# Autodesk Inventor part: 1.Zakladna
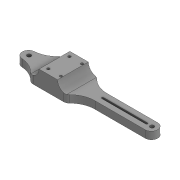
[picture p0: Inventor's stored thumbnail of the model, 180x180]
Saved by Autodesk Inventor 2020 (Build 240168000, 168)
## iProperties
Created: 2022-04
Part Number: 1.Zakladna
Material: Generic
Document SubType Name: Modeling
Designer: marti
Density: 1 g/cm^3
Appearance: Default(2)
Author: marti
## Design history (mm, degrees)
sketch "Sketch1"
  geometry: L1 (65, -25)-(-65, -25); L2 (-65, -25)-(-65, 25); L3 (-65, 25)-(65, 25); L4 (65, 25)-(65, -25); L5 (65, -25)-(-65, 25); L6 (-65, -25)-(65, 25); 1 further point
  constraints: 12 end point, 2 midpoint, 2 parallel, 1 horizontal, 1 perpendicular
  dimensions: "d0" = 130 distance of L2.end L3.end; "d1" = 50 distance of L1.end L2.end
extrude "Extrusion1" new body sketch "Sketch1" distance "d2" = 12; taper "d3" = 0 deg
sketch "Sketch2"
  geometry: L1 (-65, 25)-(-65, -25) reference; L2 (-65, -25)-(65, -25) reference; L3 (-65, 25)-(-35, 25); L4 (-35, 25)-(-35, -25); L5 (-35, -25)-(-65, -25); L6 (-65, -25)-(-65, 25); 1 further point
  constraints: 8 end point, 2 parallel, 1 horizontal, 1 perpendicular, 1 point on line
  dimensions: "d4" = 30 distance of L4.end L5.end
extrude "Extrusion2" join sketch "Sketch2" distance "d5" = 14.1; taper "d6" = 0 deg
fillet "Fillet2" dims "d32" = 14.2
sketch "Sketch4"
  geometry: L1 (-35, -25)-(-35, 25) reference; L2 (-35, 0)-(-50, 0); L3 (-65, 15)-(-35, 15); L4 (-35, 15)-(-35, -15); L5 (-35, -15)-(-65, -15); L6 (-65, -15)-(-65, 15); L7 (-65, 15)-(-35, -15); L8 (-35, 15)-(-65, -15); L9 (-35, 25)-(-20.8, 25) reference; L10 (-65, 25)-(-65, -25) reference; L11 (65, 25)-(-65, 25) reference; C1 r 2.1 at (-37.5, 17.2); C2 r 2.1 at (-37.5, -17.2); 5 further points
  constraints: 14 end point, 3 midpoint, 2 centre point, 2 horizontal, 2 parallel, 1 perpendicular
  dimensions: "d34" = 15 distance of L2.start L2.end; "d35" = 30 distance of L4.end L5.end; "d36" = 30 distance of L3.end L4.end; "d37" = 4.2 diameter of C1; "d38" = 2.5 distance from line of L1 C1.centre; "d39" = 2.2 distance from line of L3 C1.centre; "d40" = 4.2 diameter of C2 (= d37); "d41" = 2.2 distance from line of L5 C2.centre (= d39); "d42" = 2.5 distance from line of L1 C2.centre (= d38)
extrude "Extrusion4" cut sketch "Sketch4" distance "d43" = 10; taper "d44" = 0 deg
sketch "Sketch8"
  geometry: L1 (-65, -25)-(-65, 25) reference; L2 (-65, 25)-(65, 25) reference; L3 (-41.3, 21)-(-33.7, 21); L4 (-33.7, 21)-(-33.7, 13.4); L5 (-33.7, 13.4)-(-41.3, 13.4); L6 (-41.3, 13.4)-(-41.3, 21); L7 (-41.3, 21)-(-33.7, 13.4); L8 (-33.7, 21)-(-41.3, 13.4); L9 (-33.7, 15.006)-(-37.5, 12.812); L10 (-37.5, 12.812)-(-41.3, 15.006); L11 (-41.3, 15.006)-(-41.3, 19.394); L12 (-41.3, 19.394)-(-37.5, 21.588); L13 (-37.5, 21.588)-(-33.7, 19.394); L14 (-33.7, 19.394)-(-33.7, 15.006); L15 (-41.3, -13.4)-(-33.7, -13.4); L16 (-33.7, -13.4)-(-33.7, -21); L17 (-33.7, -21)-(-41.3, -21); L18 (-41.3, -21)-(-41.3, -13.4); L19 (-41.3, -13.4)-(-33.7, -21); L20 (-33.7, -13.4)-(-41.3, -21); L21 (-33.7, -19.394)-(-37.5, -21.588); L22 (-37.5, -21.588)-(-41.3, -19.394); L23 (-41.3, -19.394)-(-41.3, -15.006); L24 (-41.3, -15.006)-(-37.5, -12.812); L25 (-37.5, -12.812)-(-33.7, -15.006); L26 (-33.7, -15.006)-(-33.7, -19.394); L27 (-37.5, 17.2)-(-57.8, 17.2); L28 (-61.6, 21)-(-54, 21); L29 (-54, 21)-(-54, 13.4); L30 (-54, 13.4)-(-61.6, 13.4); L31 (-61.6, 13.4)-(-61.6, 21); L32 (-61.6, 21)-(-54, 13.4); L33 (-54, 21)-(-61.6, 13.4); L34 (-54, 15.006)-(-57.8, 12.812); L35 (-57.8, 12.812)-(-61.6, 15.006); L36 (-61.6, 15.006)-(-61.6, 19.394); L37 (-61.6, 19.394)-(-57.8, 21.588); L38 (-57.8, 21.588)-(-54, 19.394); L39 (-54, 19.394)-(-54, 15.006); L40 (-37.5, -17.2)-(-57.8, -17.2); L41 (-61.6, -13.4)-(-54, -13.4); L42 (-54, -13.4)-(-54, -21); L43 (-54, -21)-(-61.6, -21); L44 (-61.6, -21)-(-61.6, -13.4); L45 (-61.6, -13.4)-(-54, -21); L46 (-54, -13.4)-(-61.6, -21); L47 (-54, -19.394)-(-57.8, -21.588); L48 (-57.8, -21.588)-(-61.6, -19.394); L49 (-61.6, -19.394)-(-61.6, -15.006); L50 (-61.6, -15.006)-(-57.8, -12.812); L51 (-57.8, -12.812)-(-54, -15.006); L52 (-54, -15.006)-(-54, -19.394); C1 r 2.1 at (-37.5, -17.2) reference; C2 r 2 at (-37.5, -17.2); C3 r 2.1 at (-37.5, 17.2) reference; C4 r 2 at (-37.5, 17.2); 23 further points
  constraints: 100 end point, 16 midpoint, 8 parallel, 6 coincident, 5 horizontal, 5 perpendicular, 2 centre point, 52 other
  dimensions: "d58" = 7.6 distance of L4.end L5.end; "d59" = 7.6 distance of L3.end L4.end (= d58); "d60" = 7.6 distance of L16.end L17.end (= d58); "d61" = 7.6 distance of L15.end L16.end (= d58); "d62" = 20.3 distance of L27.start L27.end; "d63" = 7.6 distance of L29.end L30.end (= d58); "d64" = 7.6 distance of L28.end L29.end (= d58); "d65" = 20.3 distance of L40.start L40.end; "d66" = 7.6 distance of L42.end L43.end (= d58); "d67" = 7.6 distance of L41.end L42.end (= d58)
extrude "Extrusion6" cut sketch "Sketch8" distance "d68" = 17; taper "d69" = 0 deg
pattern_linear "Rectangular Pattern1" dims "d72" = 20.3
sketch "Sketch11"
  geometry: L1 (-65, -25)-(-65, 25) reference; L2 (-65, 25)-(-105, 25); L3 (-105, 25)-(-105, -25); L4 (-105, -25)-(-65, -25); L5 (-65, -25)-(-65, 25); L6 (65, 25)-(95, 25); L7 (95, 25)-(95, -25); L8 (95, -25)-(65, -25); L9 (65, -25)-(65, 25); 2 further points
  constraints: 16 end point, 4 parallel, 2 horizontal, 2 perpendicular
  dimensions: "d80" = 40 distance of L4.end L3.end; "d81" = 30 distance of L7.end L8.end
extrude "Extrusion8" join sketch "Sketch11" distance "d82" = 12; taper "d83" = 0 deg
sketch "Sketch12"
  geometry: L1 (95, -25)-(95, 25) reference; L2 (13.039, 1.5)-(85.139, 1.5); L3 (13.039, -1.5)-(85.139, -1.5); L4 (-20.8, -25)-(95, -25) reference; L5 (95, 25)-(-20.8, 25) reference; A1 r 1.5 centre (13.039, 0) between (13.039, 1.5) and (13.039, -1.5); A2 r 1.5 centre (85.139, 0) between (85.139, 1.5) and (85.139, -1.5); 3 further points
  constraints: 4 end point, 4 point on circle, 2 centre point, 2 tangent, 1 horizontal
  dimensions: "d87" = 3 diameter of A1; "d89" = 3 diameter of A2 (= d87); "d173" = 23.5 distance between parallel lines of L4 L3; "d174" = 72.1 distance of L2.start L2.end; "d175" = 23.5 distance between parallel lines of L2 L5
extrude "Extrusion9" cut sketch "Sketch12" distance "d90" = 12; taper "d91" = 0 deg
sketch "Sketch13"
  geometry: L1 (12.573, 2.25)-(85.139, 2.25); L2 (12.573, -2.25)-(85.139, -2.25); A1 r 2.25 centre (12.573, 0) between (12.573, 2.25) and (12.573, -2.25); A2 r 1.5 centre (85.139, 0) between (85.139, -1.5) and (85.139, 1.5) reference; A3 r 2.25 centre (85.139, 0) between (85.139, 2.25) and (85.139, -2.25); 1 further point
  constraints: 4 end point, 4 point on circle, 2 centre point, 2 tangent, 1 coincident
  dimensions: "d92" = 4.5 diameter of A1; "d93" = 4.5 diameter of A3 (= d92)
extrude "Extrusion10" cut sketch "Sketch13" distance "d94" = 8; taper "d95" = 0 deg
fillet "Fillet8" dims "d97" = 14.1
sketch "Sketch14" dims "d115" = 6.2, "d117" = 6.2
  geometry: L1 (85.139, -1.5)-(13.039, -1.5) reference; L2 (84.6, 10)-(11.1, 10); L3 (95, 25)-(-20.8, 25) reference; L4 (84.6, -10)-(11.1, -10); L5 (-5.8, 25)-(9.2, 25); L6 (-20.8, -25)-(-20.8, 25) reference; L7 (-20.8, 25)-(95, 25); L8 (95, -25)-(95, 25) reference; L9 (95, 25)-(95, -25); L10 (95, -25)-(-20.8, -25); L11 (95, -25)-(-105, -25) reference; L12 (85.239, 0)-(86.639, 0); L13 (85.239, 0)-(91.239, 0); L14 (91.239, 0)-(94.339, 0); L15 (97.439, 0)-(103.439, 0); L16 (84.6, 10)-(103.439, 10); L17 (103.439, 10)-(103.439, 0); L18 (84.6, -10)-(103.439, -10); L19 (103.439, -10)-(103.439, 0); L20 (-108.761, 0)-(-114.761, 0); L21 (-114.761, 0)-(-114.761, 11.01); A1 r 1.5 centre (85.139, 0) between (85.139, -1.5) and (85.139, 1.5) reference; A2 r 1.5 centre (13.039, 0) between (13.039, 1.5) and (13.039, -1.5) reference; A3 r 40 centre (10.429, 49.994) between (-20.8, 25) and (11.1, 10); A4 r 40 centre (10.429, -49.994) between (11.1, -10) and (-20.8, -25); 5 further points
  constraints: 32 end point, 6 horizontal, 5 perpendicular, 5 point on circle, 3 point on line, 2 centre point, 2 horizontal alignment, 1 coincident, 1 collinear, 1 vertical, 4 other
  dimensions: "d102" = 73.5 distance of L2.start L2.end; "d107" = 73.5 distance of L4.start L4.end (= d102); "d110" = 40 radius of A3; "d111" = 40 radius of A4; "d113" = 6 distance of L12.start L13.end; "d114" = 3.1 distance of L13.end L14.end; "d116" = 6 distance of L15.start L15.end; "d119" = 200 distance of point (-105.661, 0) L14.end; "d120" = 6 distance of L20.start L20.end
extrude "Extrusion11" cut sketch "Sketch14" distance "d121" = 12; taper "d122" = 0 deg
sketch "Sketch15"
  geometry: L1 (95, -10)-(95, 10) reference; L2 (95, 10)-(102.8, 10); L3 (102.8, 10)-(102.8, -10); L4 (102.8, -10)-(95, -10); L5 (95, -10)-(95, 10); L6 (102.8, 0)-(-117.2, 0); L7 (-117.2, 0)-(-117.2, 10); L8 (-105, -25)-(-105, 25) reference; L9 (-117.2, 10)-(-105, 10); L10 (-105, 10)-(-105, -10); L11 (-105, -10)-(-117.2, -10); L12 (-117.2, -10)-(-117.2, 10); 4 further points
  constraints: 20 end point, 4 parallel, 3 horizontal, 2 perpendicular, 1 midpoint, 1 point on line, 1 vertical
  dimensions: "d123" = 7.8 distance of L3.end L4.end; "d125" = 220 distance of L6.start L6.end; "d126" = 10 distance of L6.end L7.end; "d127" = 20 distance of L9.end L10.end
extrude "Extrusion12" join sketch "Sketch15" distance "d128" = 12; taper "d129" = 0 deg
sketch "Sketch16"
  geometry: L1 (102.8, -10)-(102.8, 10) reference; C1 r 3.25 at (93.7, 0); C2 r 3.25 at (-106.3, 0); 1 further point
  constraints: 2 centre point
  dimensions: "d130" = 6.5 diameter of C1; "d131" = 9.1 distance from line of L1 C1.centre; "d132" = 6.5 diameter of C2; "d133" = 200 distance of C1.centre C2.centre
extrude "Extrusion13" cut sketch "Sketch16" distance "d134" = 12; taper "d135" = 0 deg
fillet "Fillet11" dims "d148" = 10
sketch "Sketch22"
  geometry: L1 (-105, 25)-(-105, 10) reference; L2 (-107.2, 10)-(-105, 10); L3 (-105, 10)-(-105, 25); L4 (-105, 25)-(-107.2, 25); L5 (-107.2, 25)-(-107.2, 10); L6 (-105, -10)-(-107.2, -10) reference; L7 (-105, -10)-(-105, -25) reference; L8 (-107.2, -10)-(-105, -10); L9 (-105, -10)-(-105, -25); L10 (-105, -25)-(-107.2, -25); L11 (-107.2, -25)-(-107.2, -10); A1 r 10 centre (-107.2, 0) between (-107.2, 10) and (-107.2, -10) reference; 2 further points
  constraints: 16 end point, 4 parallel, 2 horizontal, 2 perpendicular
extrude "Extrusion17" join sketch "Sketch22" distance "d155" = 12; taper "d156" = 0 deg
sketch "Sketch23"
  geometry: L1 (-79.1, 25)-(-79.1, -25) reference; L2 (-107.2, 10)-(-107.2, 25) reference; L3 (-107.2, 10)-(-107.2, 25); L4 (-107.2, 25)-(-79.1, 25); L5 (-20.8, 25)-(-107.2, 25) reference; L6 (-107.2, -25)-(-107.2, -10) reference; L7 (-107.2, -10)-(-107.2, -25); L8 (-20.8, -25)-(-107.2, -25) reference; L9 (-107.2, -25)-(-79.1, -25); A1 r 10 centre (-107.2, 0) between (-107.2, 10) and (-107.2, -10) reference; A2 r 40 centre (-110.429, 49.869) between (-107.2, 10) and (-79.1, 25); A3 r 40 centre (-110.429, -49.869) between (-79.1, -25) and (-107.2, -10); 3 further points
  constraints: 8 end point, 4 collinear, 4 point on circle, 2 centre point
  dimensions: "d157" = 40 radius of A2; "d158" = 40 radius of A3
extrude "Extrusion18" cut sketch "Sketch23" distance "d159" = 12; taper "d160" = 0 deg
fillet "Fillet13" dims "d161" = 10
fillet "Fillet14" dims "d176" = 1
body "Solid1"
